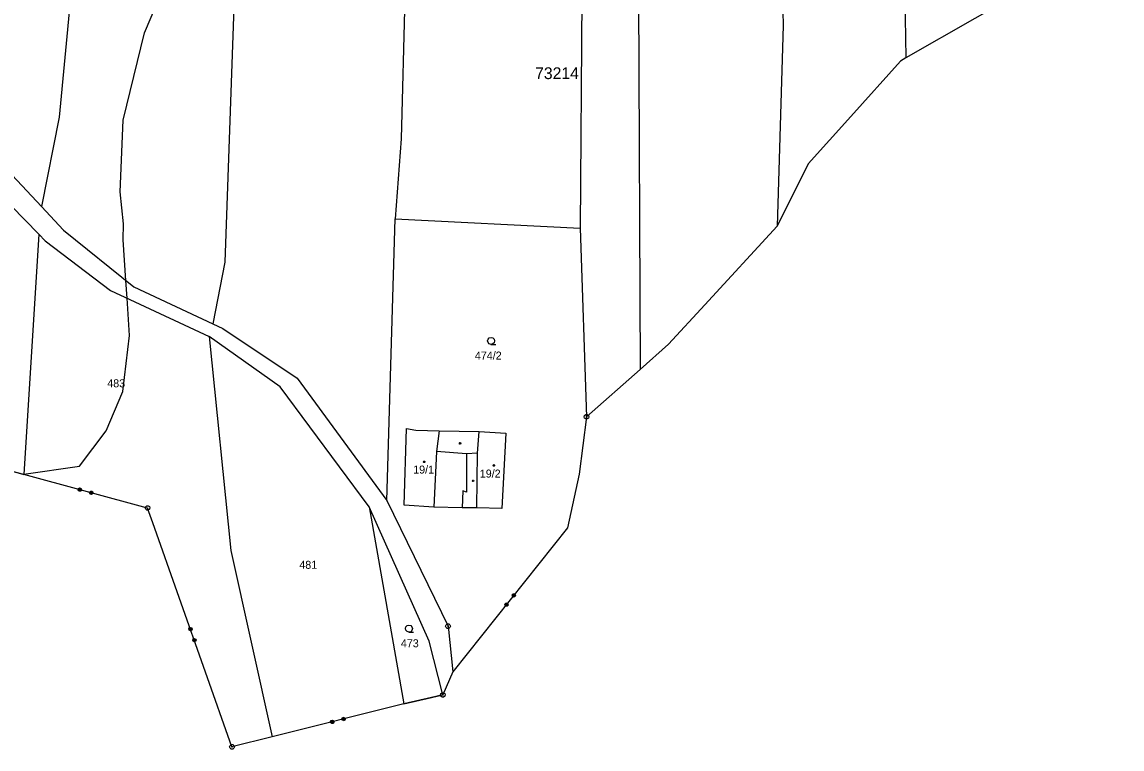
# Model space of a CAD drawing. Extents: x -760978 to -760029, y -1177282 to -1176414.
# Drawn here: x -760280.9 to -760047.3, y -1176797.1 to -1176642.6 of the extents above; entities that cross this region are included whole.
import ezdxf

# ---------------------------------------------------------------- set-up
doc = ezdxf.new("R2010")
doc.units = 0
for name, color, linetype in [('1', 7, 'Continuous'), ('11', 7, 'Continuous'), ('12', 7, 'Continuous'), ('2', 7, 'Continuous'), ('3', 7, 'Continuous'), ('4', 7, 'Continuous'), ('5', 7, 'Continuous'), ('8', 7, 'Continuous')]:
    doc.layers.add(name, color=color, linetype=linetype)

msp = doc.modelspace()

# ---------------------------------------------------------------- linework, layer by layer
at = {"layer": '1'}
for p, q in [((-760120.64, -1176586.94), (-760119.25, -1176643.36)), ((-760093.99, -1176601.49), (-760093.17, -1176650.26)), ((-760198.83, -1176606.8), (-760200.41, -1176667.45)), ((-760150.01, -1176626.07), (-760149.65, -1176716.43)), ((-760270.26, -1176633.65), (-760272.99, -1176662.87)), ((-760161.99, -1176632.33), (-760162.36, -1176686.44)), ((-760235.73, -1176635.17), (-760237.83, -1176693.67)), ((-760119.25, -1176643.36), (-760120.53, -1176685.99)), ((-760078.55, -1176641.9), (-760093.17, -1176650.26)), ((-760307.87, -1176648.55), (-760276.77, -1176681.83)), ((-760093.17, -1176650.26), (-760094.37, -1176650.94)), ((-760094.37, -1176650.94), (-760104.89, -1176662.68)), ((-760310.61, -1176653.73), (-760277.32, -1176687.71)), ((-760272.99, -1176662.87), (-760276.77, -1176681.83)), ((-760104.89, -1176662.68), (-760113.92, -1176672.76)), ((-760200.41, -1176667.45), (-760201.62, -1176684.46)), ((-760113.92, -1176672.76), (-760120.53, -1176685.99)), ((-760276.77, -1176681.83), (-760272.11, -1176686.82)), ((-760203.44, -1176744.25), (-760201.62, -1176684.46)), ((-760201.62, -1176684.46), (-760162.36, -1176686.44)), ((-760277.32, -1176687.71), (-760280.52, -1176738.75)), ((-760277.32, -1176687.71), (-760275.97, -1176689.09)), ((-760272.11, -1176686.82), (-760257.14, -1176698.87)), ((-760162.36, -1176686.44), (-760161.02, -1176726.49)), ((-760120.53, -1176685.99), (-760135.92, -1176702.73)), ((-760275.97, -1176689.09), (-760262.1, -1176699.64)), ((-760237.83, -1176693.67), (-760240.37, -1176706.77)), ((-760262.1, -1176699.64), (-760258.03, -1176701.54)), ((-760257.14, -1176698.87), (-760240.37, -1176706.77)), ((-760258.03, -1176701.54), (-760241.13, -1176709.42)), ((-760135.92, -1176702.73), (-760143.57, -1176711.05)), ((-760240.37, -1176706.77), (-760238.27, -1176707.76)), ((-760238.27, -1176707.76), (-760222.46, -1176718.26)), ((-760241.13, -1176709.42), (-760236.57, -1176754.92)), ((-760226.08, -1176720.15), (-760241.13, -1176709.42)), ((-760143.57, -1176711.05), (-760149.65, -1176716.43)), ((-760222.46, -1176718.26), (-760203.44, -1176744.25)), ((-760149.65, -1176716.43), (-760161.02, -1176726.49)), ((-760207.19, -1176745.59), (-760226.08, -1176720.15)), ((-760161.02, -1176726.49), (-760162.57, -1176738.68)), ((-760199.77, -1176745.29), (-760199.27, -1176728.94)), ((-760199.27, -1176728.94), (-760197.25, -1176729.3)), ((-760197.25, -1176729.3), (-760192.33, -1176729.5)), ((-760192.33, -1176729.5), (-760192.9, -1176733.88)), ((-760192.33, -1176729.5), (-760183.8, -1176729.61)), ((-760183.8, -1176729.61), (-760178.14, -1176729.94)), ((-760178.14, -1176729.94), (-760179.03, -1176745.97)), ((-760192.9, -1176733.88), (-760193.47, -1176745.66)), ((-760280.52, -1176738.75), (-760283.97, -1176737.82)), ((-760254.22, -1176745.86), (-760280.52, -1176738.75)), ((-760162.57, -1176738.68), (-760165.03, -1176750.06)), ((-760253.08, -1176748.99), (-760254.22, -1176745.86)), ((-760194.45, -1176774.13), (-760207.19, -1176745.59)), ((-760207.19, -1176745.59), (-760199.78, -1176787.45)), ((-760203.44, -1176744.25), (-760190.43, -1176770.96)), ((-760193.47, -1176745.66), (-760199.77, -1176745.29)), ((-760187.43, -1176745.82), (-760193.47, -1176745.66)), ((-760184.29, -1176745.83), (-760187.43, -1176745.82)), ((-760179.03, -1176745.97), (-760184.29, -1176745.83)), ((-760236.3, -1176796.59), (-760253.08, -1176748.99)), ((-760165.03, -1176750.06), (-760189.37, -1176780.69)), ((-760236.57, -1176754.92), (-760227.76, -1176794.5)), ((-760190.43, -1176770.96), (-760189.37, -1176780.69)), ((-760191.52, -1176785.57), (-760194.45, -1176774.13)), ((-760189.37, -1176780.69), (-760191.52, -1176785.57)), ((-760199.78, -1176787.45), (-760193.91, -1176786.11)), ((-760193.91, -1176786.11), (-760191.52, -1176785.57)), ((-760199.78, -1176787.45), (-760227.76, -1176794.5)), ((-760227.76, -1176794.5), (-760236.3, -1176796.59))]:
    msp.add_line(p, q, dxfattribs=at)
for points in [[(-760268.83, -1176742.24), (-760268.97, -1176742.01), (-760268.9, -1176741.75), (-760268.66, -1176741.61), (-760268.4, -1176741.68), (-760268.27, -1176741.92), (-760268.34, -1176742.18), (-760268.57, -1176742.31), (-760268.83, -1176742.24), (-760268.79, -1176742.21), (-760268.56, -1176742.27), (-760268.46, -1176742.22), (-760268.85, -1176742.11), (-760268.91, -1176742.01), (-760268.37, -1176742.16), (-760268.35, -1176742.08), (-760268.89, -1176741.94), (-760268.87, -1176741.86), (-760268.33, -1176742.01), (-760268.3, -1176741.93), (-760268.84, -1176741.78), (-760268.75, -1176741.73), (-760268.36, -1176741.83), (-760268.42, -1176741.73), (-760268.65, -1176741.67)], [(-760266.42, -1176742.89), (-760266.55, -1176742.66), (-760266.48, -1176742.4), (-760266.25, -1176742.27), (-760265.99, -1176742.34), (-760265.86, -1176742.57), (-760265.93, -1176742.83), (-760266.16, -1176742.96), (-760266.42, -1176742.89), (-760266.4, -1176742.86), (-760266.17, -1176742.92), (-760266.07, -1176742.86), (-760266.46, -1176742.76), (-760266.51, -1176742.66), (-760265.97, -1176742.81), (-760265.95, -1176742.73), (-760266.49, -1176742.58), (-760266.47, -1176742.51), (-760265.93, -1176742.65), (-760265.91, -1176742.57), (-760266.45, -1176742.43), (-760266.35, -1176742.37), (-760265.97, -1176742.48), (-760266.02, -1176742.38), (-760266.25, -1176742.32)], [(-760176.28, -1176764.74), (-760176.55, -1176764.77), (-760176.76, -1176764.6), (-760176.79, -1176764.33), (-760176.62, -1176764.12), (-760176.36, -1176764.09), (-760176.15, -1176764.26), (-760176.12, -1176764.52), (-760176.28, -1176764.74), (-760176.31, -1176764.7), (-760176.16, -1176764.52), (-760176.17, -1176764.4), (-760176.42, -1176764.72), (-760176.53, -1176764.73), (-760176.19, -1176764.29), (-760176.25, -1176764.24), (-760176.6, -1176764.68), (-760176.66, -1176764.63), (-760176.31, -1176764.19), (-760176.37, -1176764.14), (-760176.72, -1176764.58), (-760176.73, -1176764.47), (-760176.49, -1176764.15), (-760176.6, -1176764.17), (-760176.75, -1176764.36)], [(-760177.84, -1176766.69), (-760178.11, -1176766.72), (-760178.32, -1176766.56), (-760178.35, -1176766.29), (-760178.18, -1176766.08), (-760177.91, -1176766.05), (-760177.7, -1176766.22), (-760177.67, -1176766.48), (-760177.84, -1176766.69), (-760177.85, -1176766.65), (-760177.7, -1176766.46), (-760177.72, -1176766.35), (-760177.96, -1176766.66), (-760178.08, -1176766.67), (-760177.73, -1176766.23), (-760177.79, -1176766.18), (-760178.14, -1176766.62), (-760178.2, -1176766.57), (-760177.85, -1176766.13), (-760177.92, -1176766.08), (-760178.26, -1176766.52), (-760178.28, -1176766.41), (-760178.03, -1176766.1), (-760178.14, -1176766.11), (-760178.29, -1176766.3)], [(-760245.47, -1176771.55), (-760245.35, -1176771.31), (-760245.1, -1176771.22), (-760244.85, -1176771.33), (-760244.76, -1176771.59), (-760244.88, -1176771.83), (-760245.14, -1176771.92), (-760245.38, -1176771.8), (-760245.47, -1176771.55), (-760245.42, -1176771.56), (-760245.34, -1176771.79), (-760245.24, -1176771.84), (-760245.37, -1176771.46), (-760245.32, -1176771.36), (-760245.14, -1176771.89), (-760245.06, -1176771.86), (-760245.25, -1176771.33), (-760245.17, -1176771.31), (-760244.99, -1176771.83), (-760244.91, -1176771.81), (-760245.1, -1176771.28), (-760244.99, -1176771.33), (-760244.86, -1176771.7), (-760244.81, -1176771.6), (-760244.89, -1176771.38)], [(-760244.64, -1176773.91), (-760244.52, -1176773.66), (-760244.27, -1176773.57), (-760244.02, -1176773.69), (-760243.93, -1176773.94), (-760244.05, -1176774.19), (-760244.3, -1176774.28), (-760244.55, -1176774.16), (-760244.64, -1176773.91), (-760244.59, -1176773.9), (-760244.51, -1176774.13), (-760244.41, -1176774.18), (-760244.55, -1176773.8), (-760244.5, -1176773.7), (-760244.31, -1176774.23), (-760244.24, -1176774.2), (-760244.42, -1176773.67), (-760244.35, -1176773.64), (-760244.16, -1176774.17), (-760244.08, -1176774.15), (-760244.27, -1176773.62), (-760244.17, -1176773.67), (-760244.04, -1176774.04), (-760243.99, -1176773.94), (-760244.07, -1176773.72)], [(-760212.65, -1176791.02), (-760212.88, -1176790.89), (-760212.95, -1176790.62), (-760212.81, -1176790.39), (-760212.55, -1176790.33), (-760212.32, -1176790.47), (-760212.25, -1176790.73), (-760212.39, -1176790.96), (-760212.65, -1176791.02), (-760212.65, -1176790.98), (-760212.42, -1176790.92), (-760212.36, -1176790.83), (-760212.75, -1176790.93), (-760212.85, -1176790.87), (-760212.31, -1176790.73), (-760212.32, -1176790.65), (-760212.87, -1176790.79), (-760212.89, -1176790.71), (-760212.34, -1176790.58), (-760212.36, -1176790.5), (-760212.91, -1176790.63), (-760212.85, -1176790.54), (-760212.46, -1176790.44), (-760212.56, -1176790.38), (-760212.79, -1176790.44)], [(-760215.08, -1176791.63), (-760215.31, -1176791.5), (-760215.38, -1176791.23), (-760215.24, -1176791), (-760214.98, -1176790.94), (-760214.74, -1176791.08), (-760214.68, -1176791.34), (-760214.82, -1176791.57), (-760215.08, -1176791.63), (-760215.06, -1176791.59), (-760214.83, -1176791.53), (-760214.77, -1176791.43), (-760215.16, -1176791.53), (-760215.25, -1176791.47), (-760214.71, -1176791.34), (-760214.73, -1176791.26), (-760215.27, -1176791.39), (-760215.29, -1176791.32), (-760214.75, -1176791.18), (-760214.77, -1176791.1), (-760215.31, -1176791.24), (-760215.25, -1176791.14), (-760214.87, -1176791.04), (-760214.96, -1176790.99), (-760215.2, -1176791.04)]]:
    msp.add_lwpolyline(points, dxfattribs=at)
at = {"layer": '11'}
for points in [[(-760280.68, -1176738.71), (-760280.52, -1176738.68), (-760268.69, -1176737), (-760263.05, -1176729.49), (-760259.51, -1176721.08), (-760258.04, -1176709.25), (-760258.58, -1176701.28), (-760258.83, -1176697.51), (-760259.41, -1176688.89), (-760259.35, -1176685.5), (-760260.08, -1176678.71), (-760259.41, -1176663.47), (-760254.86, -1176644.92), (-760245.59, -1176623.07)], [(-760047.3, -1176624.86), (-760054.56, -1176629.9), (-760065.02, -1176634.97), (-760074.32, -1176639.48), (-760078.55, -1176641.9), (-760093.17, -1176650.26), (-760094.37, -1176650.94), (-760104.89, -1176662.68), (-760113.92, -1176672.76), (-760120.53, -1176685.99), (-760135.92, -1176702.73), (-760143.57, -1176711.05), (-760149.65, -1176716.43), (-760161.02, -1176726.49), (-760162.57, -1176738.68), (-760165.03, -1176750.06), (-760189.37, -1176780.69), (-760191.52, -1176785.57), (-760193.91, -1176786.11), (-760199.78, -1176787.45), (-760227.76, -1176794.5)], [(-760280.68, -1176738.71), (-760283.97, -1176737.82), (-760298.96, -1176737.3), (-760315.94, -1176736.72), (-760317.26, -1176736.67), (-760343.22, -1176740.55)], [(-760227.76, -1176794.5), (-760236.3, -1176796.59), (-760253.08, -1176748.99), (-760254.22, -1176745.86), (-760280.52, -1176738.75), (-760280.68, -1176738.71)]]:
    msp.add_lwpolyline(points, dxfattribs=at)
at = {"layer": '12'}
for p, q in [((-760199.77, -1176745.29), (-760199.27, -1176728.94)), ((-760199.27, -1176728.94), (-760197.25, -1176729.3)), ((-760197.25, -1176729.3), (-760192.33, -1176729.5)), ((-760192.33, -1176729.5), (-760192.9, -1176733.88)), ((-760184.14, -1176734.23), (-760183.8, -1176729.61)), ((-760183.8, -1176729.61), (-760178.14, -1176729.94)), ((-760178.14, -1176729.94), (-760179.03, -1176745.97)), ((-760192.9, -1176733.88), (-760193.47, -1176745.66)), ((-760184.29, -1176745.83), (-760184.14, -1176734.23)), ((-760193.47, -1176745.66), (-760199.77, -1176745.29)), ((-760179.03, -1176745.97), (-760184.29, -1176745.83))]:
    msp.add_line(p, q, dxfattribs=at)
at = {"layer": '3'}
for points in [[(-760181.28, -1176711.1), (-760181.66, -1176711), (-760181.93, -1176710.73), (-760182.03, -1176710.36), (-760181.93, -1176709.99), (-760181.66, -1176709.72), (-760181.29, -1176709.62), (-760180.92, -1176709.72), (-760180.65, -1176709.99), (-760180.55, -1176710.37), (-760180.65, -1176710.75), (-760180.92, -1176711.02), (-760181.3, -1176711.12), (-760180.3, -1176711.12)], [(-760198.71, -1176772.21), (-760199.09, -1176772.11), (-760199.36, -1176771.84), (-760199.46, -1176771.47), (-760199.36, -1176771.1), (-760199.09, -1176770.83), (-760198.72, -1176770.73), (-760198.35, -1176770.83), (-760198.08, -1176771.1), (-760197.98, -1176771.48), (-760198.08, -1176771.86), (-760198.35, -1176772.13), (-760198.73, -1176772.23), (-760197.73, -1176772.23)]]:
    msp.add_lwpolyline(points, dxfattribs=at)
at = {"layer": '4'}
for p, q in [((-760184.14, -1176734.23), (-760183.8, -1176729.61)), ((-760186.52, -1176734.37), (-760192.9, -1176733.88)), ((-760186.52, -1176734.37), (-760186.53, -1176742.47)), ((-760184.14, -1176734.23), (-760186.52, -1176734.37)), ((-760184.29, -1176745.83), (-760184.14, -1176734.23)), ((-760187.29, -1176742.21), (-760187.43, -1176745.82)), ((-760186.53, -1176742.47), (-760187.29, -1176742.21))]:
    msp.add_line(p, q, dxfattribs=at)
at = {"layer": '5'}
for points in [[(-760187.77, -1176731.97), (-760187.68, -1176732.12), (-760187.77, -1176732.27), (-760187.95, -1176732.27), (-760188.04, -1176732.12), (-760187.95, -1176731.97)], [(-760195.5, -1176735.88), (-760195.4, -1176735.9), (-760195.35, -1176735.99), (-760195.33, -1176736.05), (-760195.35, -1176736.14), (-760195.43, -1176736.21), (-760195.5, -1176736.22), (-760195.59, -1176736.19), (-760195.65, -1176736.13), (-760195.67, -1176736.05), (-760195.65, -1176735.96), (-760195.57, -1176735.89)], [(-760180.71, -1176736.65), (-760180.61, -1176736.67), (-760180.56, -1176736.76), (-760180.54, -1176736.82), (-760180.56, -1176736.91), (-760180.64, -1176736.98), (-760180.71, -1176736.99), (-760180.8, -1176736.96), (-760180.86, -1176736.9), (-760180.88, -1176736.82), (-760180.86, -1176736.73), (-760180.78, -1176736.66)], [(-760185, -1176739.94), (-760184.91, -1176740.09), (-760185, -1176740.24), (-760185.18, -1176740.24), (-760185.27, -1176740.09), (-760185.18, -1176739.94)]]:
    msp.add_lwpolyline(points, close=True, dxfattribs=at)
at = {"layer": '8'}
for p, q in [((-760161.14, -1176726.49), (-760160.9, -1176726.49)), ((-760254.34, -1176745.86), (-760254.1, -1176745.86)), ((-760190.55, -1176770.96), (-760190.31, -1176770.96)), ((-760191.64, -1176785.57), (-760191.4, -1176785.57)), ((-760236.42, -1176796.59), (-760236.18, -1176796.59))]:
    msp.add_line(p, q, dxfattribs=at)
for points in [[(-760160.87, -1176726.01), (-760160.62, -1176726.19), (-760160.52, -1176726.48), (-760160.62, -1176726.77), (-760160.87, -1176726.95), (-760161.18, -1176726.95), (-760161.43, -1176726.77), (-760161.53, -1176726.48), (-760161.43, -1176726.19), (-760161.18, -1176726.01)], [(-760254.07, -1176745.38), (-760253.82, -1176745.56), (-760253.72, -1176745.85), (-760253.82, -1176746.14), (-760254.07, -1176746.32), (-760254.38, -1176746.32), (-760254.63, -1176746.14), (-760254.73, -1176745.85), (-760254.63, -1176745.56), (-760254.38, -1176745.38)], [(-760190.28, -1176770.48), (-760190.03, -1176770.66), (-760189.93, -1176770.95), (-760190.03, -1176771.24), (-760190.28, -1176771.42), (-760190.59, -1176771.42), (-760190.84, -1176771.24), (-760190.94, -1176770.95), (-760190.84, -1176770.66), (-760190.59, -1176770.48)], [(-760191.37, -1176785.09), (-760191.12, -1176785.27), (-760191.02, -1176785.56), (-760191.12, -1176785.85), (-760191.37, -1176786.03), (-760191.68, -1176786.03), (-760191.93, -1176785.85), (-760192.03, -1176785.56), (-760191.93, -1176785.27), (-760191.68, -1176785.09)], [(-760236.15, -1176796.11), (-760235.9, -1176796.29), (-760235.8, -1176796.58), (-760235.9, -1176796.87), (-760236.15, -1176797.05), (-760236.46, -1176797.05), (-760236.71, -1176796.87), (-760236.81, -1176796.58), (-760236.71, -1176796.29), (-760236.46, -1176796.11)]]:
    msp.add_lwpolyline(points, close=True, dxfattribs=at)

# ---------------------------------------------------------------- texts
at = {"layer": '11'}
msp.add_text('73214', height=2.5, dxfattribs=at).set_placement((-760171.93, -1176654.76))
at = {"layer": '2'}
for s, p in [('474/2', (-760184.72, -1176714.33)), ('483', (-760262.79, -1176720.22)), ('19/1', (-760197.82, -1176738.55)), ('19/2', (-760183.68, -1176739.4)), ('481', (-760222, -1176758.78)), ('473', (-760200.44, -1176775.44))]:
    msp.add_text(s, height=1.7, dxfattribs=at).set_placement(p)

doc.saveas('drawing.dxf')
